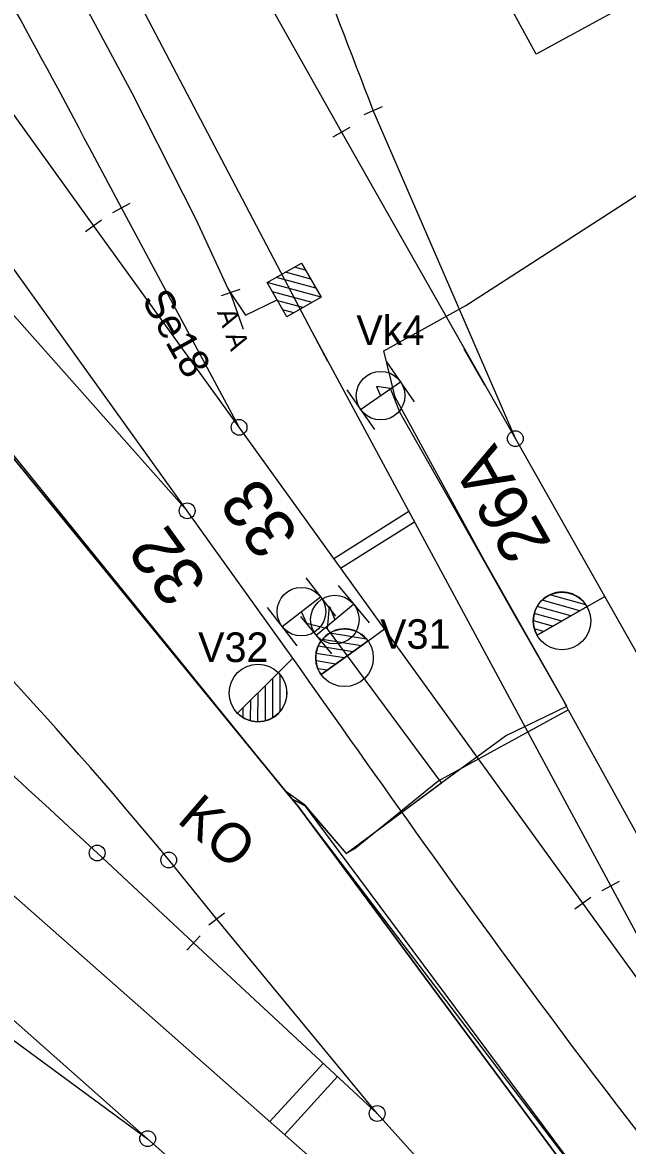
# Model space of a CAD drawing. Extents: x -496570 to -495506, y -1089156 to -1088046.
# Drawn here: x -496065.3 to -496034.6, y -1088542 to -1088485 of the extents above; entities that cross this region are included whole.
import ezdxf

# ---------------------------------------------------------------- set-up
doc = ezdxf.new("R2010")
doc.units = 0
for name, color, linetype in [('11', 7, 'Continuous'), ('14', 7, 'Continuous'), ('15', 7, 'Continuous'), ('20', 7, 'Continuous'), ('27', 7, 'Continuous'), ('39', 7, 'Continuous'), ('49', 7, 'Continuous'), ('54', 7, 'Continuous'), ('PŮVODNÍ_NÁVRH', 7, 'Continuous'), ('SEE', 7, 'Continuous')]:
    doc.layers.add(name, color=color, linetype=linetype)

msp = doc.modelspace()

# ---------------------------------------------------------------- linework, layer by layer
at = {"layer": '11'}
for p, q in [((-496049.528, -1088512.189), (-496045.706, -1088509.793)), ((-496049.175, -1088512.677), (-496045.42, -1088510.323))]:
    msp.add_line(p, q, dxfattribs=at)
for points in [[(-496052.765, -1088540.746), (-496050.065, -1088537.797)], [(-496052.027, -1088541.422), (-496049.327, -1088538.473)]]:
    msp.add_lwpolyline(points, dxfattribs=at)
at = {"layer": '14'}
for p, q in [((-496056.642, -1088531.69), (-496061.536, -1088527.124)), ((-496055.467, -1088530.486), (-496057.901, -1088527.48))]:
    msp.add_line(p, q, dxfattribs=at)
for points in [[(-496036.118, -1088555.5), (-496048.975, -1088544.1), (-496066.196, -1088528.906), (-496086.152, -1088511.349), (-496104.929, -1088494.746), (-496123.588, -1088478.229), (-496142.293, -1088461.701), (-496160.965, -1088445.175), (-496179.891, -1088428.396), (-496198.214, -1088412.189), (-496217.292, -1088395.311), (-496245.811, -1088370.064), (-496264.918, -1088353.145), (-496281.988, -1088338.018), (-496302.247, -1088320.079), (-496322.57, -1088302.076), (-496341.966, -1088284.907), (-496360.552, -1088268.447), (-496378.713, -1088252.378), (-496398.4, -1088234.928), (-496416.447, -1088218.945), (-496437.668, -1088200.162), (-496456.103, -1088183.845), (-496474.042, -1088168.071)], [(-496029.461, -1088539.924), (-496035.456, -1088528.788), (-496050.622, -1088500.683), (-496060.148, -1088482.537), (-496074.283, -1088455.273)], [(-496027.558, -1088528.593), (-496035.765, -1088514.119), (-496040.307, -1088506.105), (-496049.124, -1088490.548), (-496059.857, -1088471.5)], [(-496011.29, -1088565.037), (-496022.068, -1088550.141), (-496029.461, -1088539.924), (-496036.884, -1088529.665), (-496046.952, -1088515.759), (-496054.33, -1088505.532), (-496061.713, -1088495.299), (-496072.458, -1088480.37)], [(-496051.597, -1088517.251), (-496056.967, -1088509.766), (-496066.353, -1088496.683), (-496074.345, -1088485.622)], [(-496056.967, -1088509.766), (-496067.626, -1088497.784), (-496077.528, -1088487.052)], [(-496040.307, -1088506.105), (-496047.516, -1088489.457)], [(-496054.33, -1088505.532), (-496060.305, -1088494.392)]]:
    msp.add_lwpolyline(points, dxfattribs=at)
for centre in [(-496061.536, -1088527.124), (-496057.901, -1088527.48)]:
    msp.add_circle(centre, 0.4, dxfattribs=at)
for centre, major_axis, ratio, start_param, end_param in [((-496231.127, -1088670.242), (-155.662, 162.098), 0.998824, 4.636619, 4.761735), ((-496676.928, -1089192.103), (-679.187, 608.851), 0.993311, 4.696651, 4.713299), ((-495832.376, -1088245.472), (-305.585, 244.796), 0.998266, 1.513638, 1.639034)]:
    msp.add_ellipse(centre, major_axis=major_axis, ratio=ratio, start_param=start_param, end_param=end_param, dxfattribs=at)
for points in [[(-496060.305, -1088494.392), (-496069.107, -1088478.342), (-496082.819, -1088457.845), (-496098.833, -1088439.695), (-496101.304, -1088437.234), (-496120.979, -1088419.513)], [(-496047.516, -1088489.457), (-496054.207, -1088471.811), (-496056.848, -1088464.728), (-496059.479, -1088458.647), (-496063.984, -1088449.723)], [(-496012.573, -1088566.09), (-496028.822, -1088547.857), (-496038.151, -1088535.934), (-496051.597, -1088517.251)], [(-496063.641, -1088579.453), (-496076.368, -1088572.308), (-496088.307, -1088565.016), (-496095.758, -1088560.128), (-496107.252, -1088552.116), (-496120.36, -1088541.773)]]:
    msp.add_spline(points, degree=3, dxfattribs=at)
at = {"layer": '15'}
for p, q in [((-496050.959, -1088497.552), (-496051.517, -1088497.401)), ((-496050.431, -1088498.473), (-496052.438, -1088497.929)), ((-496050.695, -1088498.012), (-496051.977, -1088497.665)), ((-496050.168, -1088498.933), (-496052.897, -1088498.193)), ((-496050.627, -1088499.196), (-496052.634, -1088498.652)), ((-496051.088, -1088499.46), (-496052.37, -1088499.113)), ((-496051.548, -1088499.724), (-496052.106, -1088499.573)), ((-496046.844, -1088502.215), (-496045.435, -1088504.236)), ((-496048.161, -1088504.634), (-496046.139, -1088503.226)), ((-496048.865, -1088503.624), (-496047.456, -1088505.645)), ((-496050.947, -1088513.16), (-496049.441, -1088515.11)), ((-496049.306, -1088513.556), (-496047.735, -1088515.455)), ((-496052.897, -1088514.666), (-496051.391, -1088516.616)), ((-496052.144, -1088515.641), (-496050.194, -1088514.135)), ((-496050.419, -1088516.076), (-496048.521, -1088514.506)), ((-496051.205, -1088515.127), (-496049.634, -1088517.026))]:
    msp.add_line(p, q, dxfattribs=at)
msp.add_lwpolyline([(-496051.903, -1088499.927), (-496052.897, -1088498.193), (-496051.162, -1088497.198), (-496050.168, -1088498.933)], close=True, dxfattribs=at)
msp.add_lwpolyline([(-496051.903, -1088499.927), (-496052.897, -1088498.193), (-496051.162, -1088497.198), (-496050.168, -1088498.933)], close=True, dxfattribs=at)
msp.add_lwpolyline([(-496051.903, -1088499.927), (-496052.897, -1088498.193), (-496051.162, -1088497.198), (-496050.168, -1088498.933), (-496051.903, -1088499.927)], dxfattribs=at)
msp.add_lwpolyline([(-496051.903, -1088499.927), (-496052.897, -1088498.193), (-496051.162, -1088497.198), (-496050.168, -1088498.933), (-496051.903, -1088499.927)], dxfattribs=at)
for centre in [(-496047.147, -1088503.926), (-496051.166, -1088514.884), (-496049.467, -1088515.287)]:
    msp.add_circle(centre, 1.232, dxfattribs=at)
at = {"layer": '20'}
for p, q in [((-496054.3, -1088498.535), (-496055.242, -1088498.869)), ((-496054.112, -1088500.569), (-496054.771, -1088498.702))]:
    msp.add_line(p, q, dxfattribs=at)
at = {"layer": '27'}
for p, q in [((-496047.975, -1088489.656), (-496047.057, -1088489.258)), ((-496049.559, -1088490.795), (-496048.689, -1088490.301)), ((-496060.746, -1088494.628), (-496059.864, -1088494.156)), ((-496062.119, -1088495.592), (-496061.307, -1088495.006)), ((-496036.722, -1088514.535), (-496038.551, -1088514.028)), ((-496036.658, -1088514.629), (-496035.765, -1088514.119)), ((-496036.659, -1088514.629), (-496039.206, -1088516.071)), ((-496039.206, -1088516.071), (-496036.659, -1088514.629)), ((-496037.49, -1088515.099), (-496039.202, -1088514.627)), ((-496037.028, -1088514.839), (-496038.954, -1088514.306)), ((-496036.659, -1088514.629), (-496036.659, -1088514.629)), ((-496037.952, -1088515.361), (-496039.344, -1088514.976)), ((-496047.784, -1088516.363), (-496046.952, -1088515.759)), ((-496038.413, -1088515.622), (-496039.392, -1088515.351)), ((-496038.875, -1088515.884), (-496039.335, -1088515.757)), ((-496047.785, -1088516.363), (-496050.159, -1088518.075)), ((-496050.159, -1088518.075), (-496047.785, -1088516.363)), ((-496048.129, -1088516.612), (-496050.102, -1088516.293)), ((-496047.858, -1088516.277), (-496049.732, -1088515.973)), ((-496047.785, -1088516.363), (-496047.785, -1088516.363)), ((-496048.559, -1088516.922), (-496050.313, -1088516.639)), ((-496052.329, -1088517.974), (-496051.597, -1088517.251)), ((-496049.421, -1088517.542), (-496050.422, -1088517.38)), ((-496048.991, -1088517.232), (-496050.416, -1088517.002)), ((-496052.329, -1088517.974), (-496054.406, -1088520.038)), ((-496054.406, -1088520.038), (-496052.329, -1088517.974)), ((-496052.329, -1088517.974), (-496052.329, -1088517.974)), ((-496052.255, -1088518.06), (-496052.261, -1088519.958)), ((-496049.851, -1088517.853), (-496050.322, -1088517.777)), ((-496053.007, -1088518.647), (-496053.014, -1088520.423)), ((-496052.631, -1088518.274), (-496052.638, -1088520.271)), ((-496053.383, -1088519.021), (-496053.389, -1088520.465)), ((-496054.136, -1088519.769), (-496054.138, -1088520.246)), ((-496053.758, -1088519.395), (-496053.763, -1088520.411)), ((-496035.896, -1088529.025), (-496035.016, -1088528.551)), ((-496037.289, -1088529.958), (-496036.479, -1088529.372)), ((-496055.072, -1088530.179), (-496055.862, -1088530.793)), ((-496056.299, -1088531.326), (-496056.985, -1088532.054))]:
    msp.add_line(p, q, dxfattribs=at)
for points in [[(-496040.307, -1088506.105), (-496047.516, -1088489.457)], [(-496035.765, -1088514.119), (-496040.307, -1088506.105), (-496049.124, -1088490.548)], [(-496054.33, -1088505.532), (-496060.305, -1088494.392)], [(-496046.952, -1088515.759), (-496054.33, -1088505.532), (-496061.713, -1088495.299)], [(-496051.597, -1088517.251), (-496056.967, -1088509.766), (-496066.353, -1088496.683)], [(-496056.967, -1088509.766), (-496067.626, -1088497.784)], [(-496048.752, -1088550.648), (-496058.972, -1088541.619), (-496073.961, -1088528.378)], [(-496029.461, -1088539.924), (-496035.456, -1088528.788)], [(-496075.077, -1088529.806), (-496058.972, -1088541.619)], [(-496022.068, -1088550.141), (-496029.461, -1088539.924), (-496036.884, -1088529.665)], [(-496038.935, -1088549.668), (-496047.32, -1088540.34), (-496055.467, -1088530.486)], [(-496047.32, -1088540.34), (-496056.642, -1088531.69)]]:
    msp.add_lwpolyline(points, dxfattribs=at)
for centre, radius in [((-496054.33, -1088505.532), 0.4), ((-496040.307, -1088506.105), 0.4), ((-496056.967, -1088509.766), 0.4), ((-496037.94, -1088515.353), 1.462), ((-496048.979, -1088517.223), 1.462), ((-496053.372, -1088519.012), 1.462), ((-496047.32, -1088540.34), 0.4), ((-496058.972, -1088541.619), 0.4)]:
    msp.add_circle(centre, radius, dxfattribs=at)
for centre, start, end in [((-496037.932, -1088515.35), 29.5623, 209.5231), ((-496048.972, -1088517.219), 35.8271, 215.788), ((-496053.367, -1088519.005), 224.8185, 44.7793)]:
    msp.add_arc(centre, 1.464, start, end, dxfattribs=at)
at = {"layer": '39'}
msp.add_lwpolyline([(-496032.231, -1088482.763), (-496039.242, -1088486.597), (-496055.259, -1088457.292), (-496062.86, -1088443.337), (-496069.929, -1088447.197), (-496080.182, -1088428.388), (-496065.919, -1088420.663), (-496032.231, -1088482.763)], dxfattribs=at)
at = {"layer": '49'}
for points in [[(-496049.828, -1088502.201), (-496050.622, -1088500.683)], [(-496041.859, -1088503.393), (-496042.898, -1088501.564)]]:
    msp.add_lwpolyline(points, dxfattribs=at)
at = {"layer": '54'}
for points in [[(-496035.05, -1088546.1), (-496051.31, -1088524.79), (-496051.95, -1088524), (-496075.46, -1088495.01), (-496082.21, -1088487.56), (-496083.74, -1088486.13), (-496115.78, -1088449.34), (-496116.666, -1088448.476), (-496129.8, -1088436.28), (-496168.994, -1088401.872), (-496172.14, -1088399.257), (-496208.919, -1088366.316), (-496218.168, -1088358.05), (-496219.89, -1088357.07), (-496221.818, -1088357.316), (-496227.949, -1088364.044), (-496231.283, -1088367.587), (-496235.293, -1088372.311), (-496239.162, -1088376.183), (-496245.965, -1088384.343), (-496248.182, -1088386.654), (-496249.196, -1088385.882), (-496252.528, -1088385.701), (-496270.673, -1088369.666)], [(-496249.196, -1088385.882), (-496248.182, -1088386.654), (-496245.965, -1088384.343), (-496239.162, -1088376.183), (-496235.293, -1088372.311), (-496231.283, -1088367.587), (-496227.949, -1088364.044), (-496221.818, -1088357.316), (-496219.9, -1088357.08), (-496218.168, -1088358.05), (-496208.919, -1088366.316), (-496172.14, -1088399.257), (-496168.994, -1088401.872), (-496129.8, -1088436.28), (-496116.666, -1088448.476), (-496115.78, -1088449.34), (-496093.74, -1088475.27), (-496082.49, -1088487.89), (-496075.35, -1088495.41), (-496051.95, -1088524), (-496051.31, -1088524.79), (-496034.93, -1088546.87)], [(-496035.05, -1088546.1), (-496051.01, -1088524.68), (-496051.95, -1088524), (-496075.35, -1088495.41), (-496082.21, -1088487.56), (-496083.74, -1088486.13), (-496093.74, -1088475.27), (-496115.78, -1088449.34)], [(-496092.632, -1088473.615), (-496092.88, -1088473.387), (-496093.03, -1088474.095), (-496089.266, -1088478.913), (-496086.51, -1088481.943), (-496082.858, -1088477.58), (-496079.383, -1088474.861), (-496075.731, -1088472.172), (-496070.715, -1088468.877), (-496066.112, -1088476.72), (-496059.764, -1088488.605), (-496056.52, -1088494.969), (-496054.901, -1088498.484), (-496054.771, -1088498.702), (-496054.01, -1088499.84), (-496052.4, -1088499.06)], [(-496051.612, -1088524.403), (-496051.011, -1088524.683), (-496048.902, -1088527.15), (-496048.461, -1088526.891), (-496044.241, -1088523.485), (-496037.63, -1088519.866), (-496037.82, -1088519.48), (-496040.45, -1088514.86), (-496043.64, -1088509.23), (-496046.15, -1088504.8), (-496046.64, -1088503.57), (-496047.35, -1088503.46), (-496047.15, -1088503.93)], [(-496049.836, -1088515.749), (-496049.74, -1088514.63), (-496049.47, -1088515.291)], [(-496048.902, -1088527.15), (-496044.057, -1088523.574), (-496049.836, -1088515.749), (-496050.89, -1088515.49), (-496051.169, -1088514.888)], [(-496037.63, -1088519.866), (-496029.46, -1088534.646), (-496022.279, -1088546.306), (-496021.845, -1088547.068)]]:
    msp.add_lwpolyline(points, dxfattribs=at)
at = {"layer": 'PŮVODNÍ_NÁVRH'}
for points in [[(-496015.829, -1088567.72), (-496024.83, -1088557.73), (-496034.93, -1088546.87), (-496051.31, -1088524.79), (-496051.95, -1088524), (-496075.35, -1088495.41), (-496082.21, -1088487.56), (-496083.78, -1088486.19), (-496093.74, -1088475.27), (-496115.78, -1088449.34)], [(-496046.99, -1088501.65), (-496042.82, -1088499.36), (-496035.34, -1088494.54), (-496026.68, -1088488.94), (-496017.01, -1088483.74), (-496015.61, -1088482.89), (-496011.64, -1088481.25), (-496002.63, -1088476.82)], [(-496048.461, -1088526.891), (-496044.241, -1088523.485), (-496037.63, -1088519.866)]]:
    msp.add_lwpolyline(points, dxfattribs=at)
at = {"layer": 'SEE'}
for points in [[(-496051.62, -1088524.39), (-496051.01, -1088524.72), (-496048.89, -1088527.16), (-496044.09, -1088523.58), (-496040.8, -1088521.19), (-496037.7, -1088519.67), (-496041.89, -1088512.27), (-496046.41, -1088504), (-496046.99, -1088501.65), (-496042.82, -1088499.36), (-496035.34, -1088494.54), (-496026.68, -1088488.94), (-496017.01, -1088483.74), (-496015.61, -1088482.89), (-496011.64, -1088481.25), (-496002.63, -1088476.82), (-496002.82, -1088476.02), (-496008.96, -1088461.03), (-496015.33, -1088446.34), (-496027.34, -1088417), (-496033.98, -1088400.73), (-496038.24, -1088391.07)], [(-496115.78, -1088449.34), (-496093.74, -1088475.27), (-496084.13, -1088486.54), (-496082.5, -1088487.93), (-496075.35, -1088495.41), (-496051.95, -1088524), (-496051.31, -1088524.79), (-496034.93, -1088546.87)], [(-496115.78, -1088449.34), (-496093.74, -1088475.27), (-496084.13, -1088486.54), (-496082.5, -1088487.93), (-496075.35, -1088495.41), (-496051.95, -1088524), (-496051.31, -1088524.79), (-496034.93, -1088546.87)]]:
    msp.add_lwpolyline(points, dxfattribs=at)

# ---------------------------------------------------------------- texts
at = {"layer": '14'}
msp.add_text('KO', height=2, rotation=319.4182, dxfattribs=at).set_placement((-496057.537, -1088525.525))
at = {"layer": '15'}
for s, p in [('Vk4', (-496048.376, -1088501.358)), ('V31', (-496047.169, -1088516.768)), ('V32', (-496056.407, -1088517.438))]:
    msp.add_text(s, height=1.5, dxfattribs=at).set_placement(p)
at = {"layer": '20'}
for s, height, rotation, p in [('Se18', 1.5, 299.1526, (-496059.293, -1088499.062)), ('  A A', 1, 289.4544, (-496055.704, -1088498.986))]:
    msp.add_text(s, height=height, rotation=rotation, dxfattribs=at).set_placement(p)
at = {"layer": '27'}
for s, rotation, p in [('26A', 119.5427, (-496038.435, -1088511.449)), ('33', 125.8076, (-496051.224, -1088510.953)), ('32', 125.657, (-496055.869, -1088513.38))]:
    msp.add_text(s, height=2.5, rotation=rotation, dxfattribs=at).set_placement(p)

doc.saveas('drawing.dxf')
